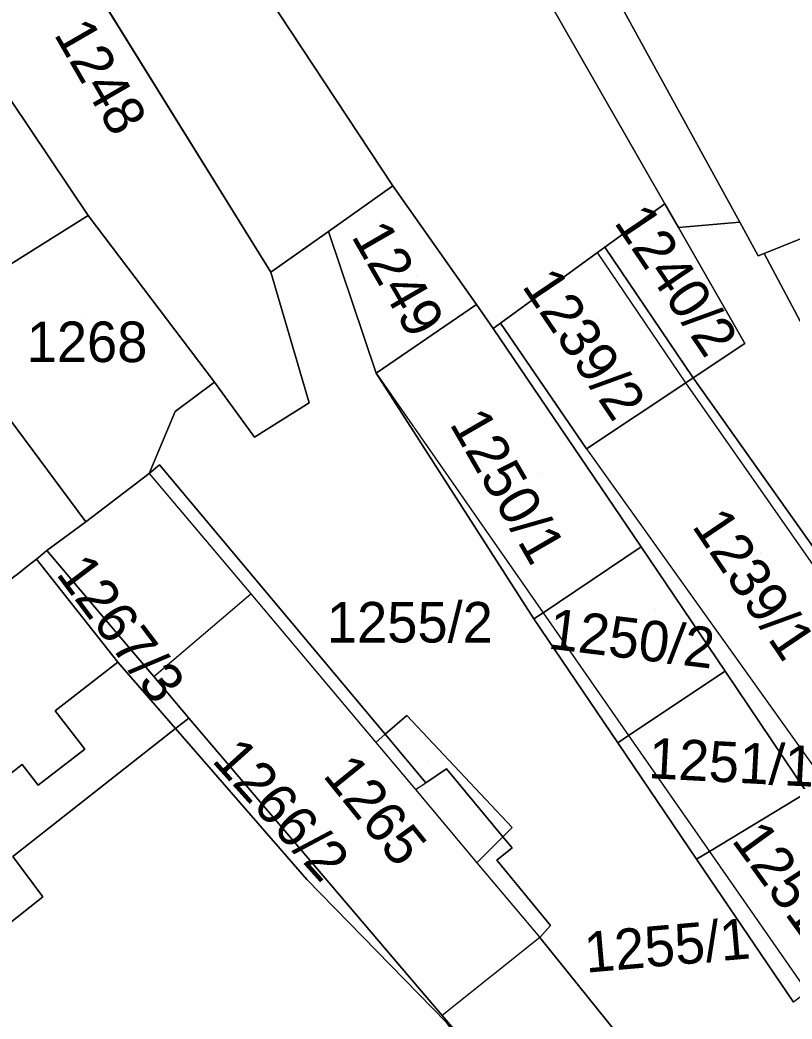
# Model space of a CAD drawing. Extents: x -263943 to -261149, y -1236934 to -1230686.
# Drawn here: x -263003.38 to -262965.33, y -1235458.41 to -1235409.18 of the extents above; entities that cross this region are included whole.
import ezdxf

# ---------------------------------------------------------------- set-up
doc = ezdxf.new("R2010")
doc.units = 0
for name, color, linetype in [('body_kn', 7, 'Continuous'), ('kladpar_druhypozemkov', 7, 'Continuous'), ('kladpar_hranice', 7, 'Continuous'), ('kladpar_parcelnecisla', 7, 'Continuous'), ('kladpar_plochy', 7, 'Continuous'), ('kladpar_sipky', 7, 'Continuous'), ('zappar_hrandruhpozemk', 7, 'Continuous')]:
    doc.layers.add(name, color=color, linetype=linetype)

msp = doc.modelspace()

# ---------------------------------------------------------------- linework, layer by layer
at = {"layer": 'body_kn'}
for p, q in [((-262985, -1235417.35), (-262985, -1235417.35)), ((-262985, -1235417.35), (-262985, -1235417.35)), ((-262971.6, -1235418.24), (-262971.6, -1235418.24)), ((-262971.6, -1235418.24), (-262971.6, -1235418.24)), ((-263000.02, -1235418.81), (-263000.02, -1235418.81)), ((-262970.93, -1235419.41), (-262970.93, -1235419.41)), ((-262967.9, -1235419.14), (-262967.9, -1235419.14)), ((-262988.18, -1235419.6), (-262988.18, -1235419.6)), ((-262974.55, -1235420.38), (-262974.55, -1235420.38)), ((-262974.91, -1235420.64), (-262974.91, -1235420.64)), ((-262966.99, -1235420.8), (-262966.99, -1235420.8)), ((-262966.7, -1235420.68), (-262966.7, -1235420.68)), ((-262991.01, -1235421.6), (-262991.01, -1235421.6)), ((-262991.01, -1235421.6), (-262991.01, -1235421.6)), ((-262980.88, -1235423.2), (-262980.88, -1235423.2)), ((-262980.05, -1235424.38), (-262980.05, -1235424.38)), ((-262979.69, -1235424.12), (-262979.69, -1235424.12)), ((-262979.69, -1235424.12), (-262979.69, -1235424.12)), ((-262967.66, -1235425.12), (-262967.66, -1235425.12)), ((-262985.82, -1235426.59), (-262985.82, -1235426.59)), ((-262985.82, -1235426.59), (-262985.82, -1235426.59)), ((-262970.2, -1235426.82), (-262970.2, -1235426.82)), ((-262970.2, -1235426.82), (-262970.2, -1235426.82)), ((-262993.8, -1235427.03), (-262993.8, -1235427.03)), ((-262993.8, -1235427.03), (-262993.8, -1235427.03)), ((-262970.57, -1235427.06), (-262970.57, -1235427.06)), ((-262970.57, -1235427.06), (-262970.57, -1235427.06)), ((-262989.12, -1235428.04), (-262989.12, -1235428.04)), ((-262995.74, -1235428.47), (-262995.74, -1235428.47)), ((-262991.83, -1235429.74), (-262991.83, -1235429.74)), ((-262975.45, -1235430.31), (-262975.45, -1235430.31)), ((-262975.45, -1235430.31), (-262975.45, -1235430.31)), ((-262996.5, -1235431.1), (-262996.5, -1235431.1)), ((-262997.01, -1235431.53), (-262997.01, -1235431.53)), ((-262997.01, -1235431.53), (-262997.01, -1235431.53)), ((-263000.14, -1235433.91), (-263000.14, -1235433.91)), ((-263000.14, -1235433.91), (-263000.14, -1235433.91)), ((-262972.77, -1235435.14), (-262972.77, -1235435.14)), ((-263002.57, -1235435.75), (-263002.57, -1235435.75)), ((-263002.57, -1235435.75), (-263002.57, -1235435.75)), ((-263002.05, -1235435.33), (-263002.05, -1235435.33)), ((-263002.99, -1235436.08), (-263002.99, -1235436.08)), ((-263002.99, -1235436.08), (-263002.99, -1235436.08)), ((-262992.01, -1235437.46), (-262992.01, -1235437.46)), ((-262992.01, -1235437.46), (-262992.01, -1235437.46)), ((-262978.06, -1235438.7), (-262978.06, -1235438.7)), ((-262977.6, -1235438.39), (-262977.6, -1235438.39)), ((-262977.6, -1235438.39), (-262977.6, -1235438.39)), ((-262997.86, -1235440.27), (-262997.86, -1235440.27)), ((-262998.56, -1235440.83), (-262998.56, -1235440.83)), ((-262999.43, -1235441.5), (-262999.43, -1235441.5)), ((-262996.79, -1235441.54), (-262996.79, -1235441.54)), ((-262996.79, -1235441.54), (-262996.79, -1235441.54)), ((-262968.63, -1235441.27), (-262968.63, -1235441.27)), ((-263001.65, -1235443.23), (-263001.65, -1235443.23)), ((-262995.06, -1235443.59), (-262995.06, -1235443.59)), ((-262984.32, -1235443.46), (-262984.32, -1235443.46)), ((-262995.72, -1235444.1), (-262995.72, -1235444.1)), ((-262995.72, -1235444.1), (-262995.72, -1235444.1)), ((-262985.38, -1235444.38), (-262985.38, -1235444.38)), ((-262973.38, -1235444.45), (-262973.38, -1235444.45)), ((-262973.38, -1235444.45), (-262973.38, -1235444.45)), ((-263000.19, -1235445.11), (-263000.19, -1235445.11)), ((-262985.84, -1235444.79), (-262985.84, -1235444.79)), ((-262985.84, -1235444.79), (-262985.84, -1235444.79)), ((-262973.92, -1235444.81), (-262973.92, -1235444.81)), ((-262973.92, -1235444.81), (-262973.92, -1235444.81)), ((-263003.27, -1235445.87), (-263003.27, -1235445.87)), ((-262982.36, -1235446.09), (-262982.36, -1235446.09)), ((-262982.36, -1235446.09), (-262982.36, -1235446.09)), ((-263002.48, -1235446.89), (-263002.48, -1235446.89)), ((-262983.38, -1235446.77), (-262983.38, -1235446.77)), ((-262983.89, -1235447.11), (-262983.89, -1235447.11)), ((-262983.89, -1235447.11), (-262983.89, -1235447.11)), ((-262979.12, -1235448.97), (-262979.12, -1235448.97)), ((-262979.58, -1235449.43), (-262979.58, -1235449.43)), ((-262979.58, -1235449.43), (-262979.58, -1235449.43)), ((-262979.12, -1235449.98), (-262979.12, -1235449.98)), ((-262979.12, -1235449.98), (-262979.12, -1235449.98)), ((-262970.03, -1235450.54), (-262970.03, -1235450.54)), ((-262970.03, -1235450.54), (-262970.03, -1235450.54)), ((-262969.4, -1235450.16), (-262969.4, -1235450.16)), ((-262969.4, -1235450.16), (-262969.4, -1235450.16)), ((-262980.86, -1235450.71), (-262980.86, -1235450.71)), ((-262979.88, -1235450.58), (-262979.88, -1235450.58)), ((-262989.24, -1235451.54), (-262989.24, -1235451.54)), ((-263002.26, -1235452.39), (-263002.26, -1235452.39)), ((-262977.24, -1235453.8), (-262977.24, -1235453.8)), ((-262977.75, -1235454.39), (-262977.75, -1235454.39)), ((-262977.75, -1235454.39), (-262977.75, -1235454.39)), ((-262982.57, -1235458.24), (-262982.57, -1235458.24))]:
    msp.add_line(p, q, dxfattribs=at)
at = {"layer": 'kladpar_druhypozemkov'}
for p, q in [((-262970.63, -1235421.43), (-262970.63, -1235421.43)), ((-262983.83, -1235421.82), (-262983.83, -1235421.82)), ((-263000.34, -1235423.74), (-263000.34, -1235423.74)), ((-262974.88, -1235423.93), (-262974.88, -1235423.93)), ((-262977.82, -1235431.53), (-262977.82, -1235431.53)), ((-262966.9, -1235435.4), (-262966.9, -1235435.4)), ((-263001.05, -1235437.03), (-263001.05, -1235437.03)), ((-262972.04, -1235438.24), (-262972.04, -1235438.24)), ((-262969.12, -1235445.26), (-262969.12, -1235445.26)), ((-262983.25, -1235445.69), (-262983.25, -1235445.69)), ((-262993.23, -1235446.29), (-262993.23, -1235446.29)), ((-262985.11, -1235447.63), (-262985.11, -1235447.63)), ((-262972.94, -1235453.94), (-262972.94, -1235453.94))]:
    msp.add_line(p, q, dxfattribs=at)
at = {"layer": 'kladpar_hranice'}
msp.add_line((-262988.18, -1235419.6), (-262991.01, -1235421.6), dxfattribs=at)
for points in [[(-262991.01, -1235421.6), (-263006.36, -1235396.86), (-263012.04, -1235400.51), (-263013.75, -1235397.97), (-263020.74, -1235387.21), (-263026.28, -1235378.22), (-263034.8, -1235364.66), (-263018.87, -1235356.25), (-263013.95, -1235366.36), (-263010.5, -1235373.45), (-262997.36, -1235398.62), (-262985, -1235417.35), (-262988.18, -1235419.6)], [(-262971.6, -1235418.24), (-262986.86, -1235391.57), (-262995.81, -1235375.55), (-263001.69, -1235369.37), (-262997.27, -1235369.36), (-262996.85, -1235369.53), (-262994.9, -1235368.6), (-262991.76, -1235367.15), (-262991.67, -1235370.46), (-262991.57, -1235373.85), (-262990.55, -1235377.84), (-262980.56, -1235396.06), (-262967.9, -1235419.14), (-262970.93, -1235419.41), (-262971.6, -1235418.24)], [(-262959.63, -1235414.42), (-262958.44, -1235417.35), (-262966.7, -1235420.68), (-262966.99, -1235420.8), (-262967.9, -1235419.14), (-262980.56, -1235396.06), (-262970.22, -1235390.61), (-262963.9, -1235405.36), (-262962.96, -1235407.48), (-262959.63, -1235414.42)], [(-262979.69, -1235424.12), (-262980.05, -1235424.38), (-262980.88, -1235423.2), (-262985, -1235417.35), (-262997.36, -1235398.62), (-262986.86, -1235391.57), (-262971.6, -1235418.24), (-262974.55, -1235420.38), (-262974.91, -1235420.64), (-262979.69, -1235424.12)], [(-262993.8, -1235427.03), (-263000.02, -1235418.81), (-263005.72, -1235410.34), (-263007.22, -1235408.16), (-263012.04, -1235400.51), (-263006.36, -1235396.86), (-262991.01, -1235421.6), (-262989.12, -1235428.04), (-262991.83, -1235429.74), (-262993.8, -1235427.03)], [(-263028.99, -1235436.97), (-263030.68, -1235438.03), (-263032.22, -1235434.75), (-263022.27, -1235429.8), (-263021.19, -1235431.41), (-263016.12, -1235428.08), (-263018.16, -1235424.78), (-263022.63, -1235427.75), (-263022.6, -1235425.3), (-263016.14, -1235421.87), (-263016.64, -1235420.94), (-263012.58, -1235418.83), (-263013.18, -1235417.56), (-263005.72, -1235410.34), (-263000.02, -1235418.81), (-263007.76, -1235423.66), (-263028.99, -1235436.97)], [(-262985, -1235417.35), (-262980.88, -1235423.2), (-262985.82, -1235426.59), (-262988.18, -1235419.6), (-262985, -1235417.35)], [(-262956.21, -1235422.81), (-262953.64, -1235429.76), (-262960.42, -1235432.49), (-262966.7, -1235420.68), (-262958.44, -1235417.35), (-262957.93, -1235418.59), (-262957.75, -1235419.04), (-262956.21, -1235422.81)], [(-262970.2, -1235426.82), (-262974.55, -1235420.38), (-262971.6, -1235418.24), (-262970.93, -1235419.41), (-262967.66, -1235425.12), (-262970.2, -1235426.82)], [(-263000.14, -1235433.91), (-263007.76, -1235423.66), (-263000.02, -1235418.81), (-262993.8, -1235427.03), (-262995.74, -1235428.47), (-262997.01, -1235431.53), (-263000.14, -1235433.91)], [(-262950.87, -1235452.84), (-262947.38, -1235460.65), (-262944.89, -1235466.22), (-262947.49, -1235467.99), (-262942.82, -1235478.02), (-262939.2, -1235485.83), (-262943.02, -1235478.13), (-262948, -1235468.07), (-262950.21, -1235463.4), (-262953.13, -1235457.23), (-262956.06, -1235451.05), (-262956.46, -1235450.2), (-262957.6, -1235445.57), (-262957.16, -1235445.2), (-262970.2, -1235426.82), (-262967.66, -1235425.12), (-262970.93, -1235419.41), (-262967.9, -1235419.14), (-262966.99, -1235420.8), (-262966.7, -1235420.68), (-262960.42, -1235432.49), (-262954.79, -1235442.65), (-262955.3, -1235442.91), (-262950.87, -1235452.84)], [(-262973.06, -1235460.23), (-262977.75, -1235454.39), (-262977.24, -1235453.8), (-262979.88, -1235450.58), (-262979.12, -1235449.98), (-262979.58, -1235449.43), (-262979.12, -1235448.97), (-262984.32, -1235443.46), (-262985.38, -1235444.38), (-262996.5, -1235431.1), (-262997.01, -1235431.53), (-262995.74, -1235428.47), (-262993.8, -1235427.03), (-262991.83, -1235429.74), (-262989.12, -1235428.04), (-262991.01, -1235421.6), (-262988.18, -1235419.6), (-262985.82, -1235426.59), (-262978.06, -1235438.7), (-262973.92, -1235444.81), (-262970.03, -1235450.54), (-262965.26, -1235457.59)], [(-262979.69, -1235424.12), (-262974.91, -1235420.64), (-262974.55, -1235420.38), (-262970.2, -1235426.82), (-262970.57, -1235427.06), (-262975.45, -1235430.31), (-262979.69, -1235424.12)], [(-262977.6, -1235438.39), (-262978.06, -1235438.7), (-262985.82, -1235426.59), (-262980.88, -1235423.2), (-262980.05, -1235424.38), (-262972.77, -1235435.14), (-262977.6, -1235438.39)], [(-263002.99, -1235436.08), (-263003.52, -1235436.5), (-263003.62, -1235436.58), (-263011.28, -1235442.62), (-263021.64, -1235450.8), (-263023.21, -1235451.7), (-263025.64, -1235447.26), (-263027.27, -1235444.21), (-263027.78, -1235443.11), (-263030.68, -1235438.03), (-263028.99, -1235436.97), (-263007.76, -1235423.66), (-263000.14, -1235433.91), (-263002.05, -1235435.33), (-263002.57, -1235435.75), (-263002.99, -1235436.08)], [(-262961.15, -1235452.34), (-262964.59, -1235447.25), (-262968.63, -1235441.27), (-262972.77, -1235435.14), (-262980.05, -1235424.38), (-262979.69, -1235424.12), (-262975.45, -1235430.31), (-262970.57, -1235427.06), (-262970.2, -1235426.82), (-262957.16, -1235445.2), (-262957.6, -1235445.57), (-262956.46, -1235450.2), (-262961.15, -1235452.34)], [(-262979.12, -1235449.98), (-262979.88, -1235450.58), (-262977.24, -1235453.8), (-262977.75, -1235454.39), (-262973.06, -1235460.23), (-262977.46, -1235463.99), (-262979.42, -1235461.94), (-262982.57, -1235458.24), (-262995.06, -1235443.59), (-262996.79, -1235441.54), (-262997.86, -1235440.27), (-263002.05, -1235435.33), (-263000.14, -1235433.91), (-262997.01, -1235431.53), (-262996.5, -1235431.1), (-262985.38, -1235444.38), (-262983.38, -1235446.77), (-262982.36, -1235446.09), (-262979.58, -1235449.43), (-262979.12, -1235449.98)], [(-262973.92, -1235444.81), (-262978.06, -1235438.7), (-262977.6, -1235438.39), (-262972.77, -1235435.14), (-262968.63, -1235441.27), (-262973.38, -1235444.45), (-262973.92, -1235444.81)], [(-263021.64, -1235450.8), (-263011.28, -1235442.62), (-263003.62, -1235436.58), (-263003.52, -1235436.5), (-263002.99, -1235436.08), (-263002.57, -1235435.75), (-262998.56, -1235440.83), (-262999.43, -1235441.5), (-263001.65, -1235443.23), (-263000.19, -1235445.11), (-263002.48, -1235446.89), (-263003.27, -1235445.87), (-263006.08, -1235448.06), (-263006.74, -1235447.2), (-263007.82, -1235448.04), (-263007.16, -1235448.9), (-263008.79, -1235450.17), (-263014.93, -1235454.95), (-263015.6, -1235454.1), (-263017.55, -1235455.62), (-263021.64, -1235450.8)], [(-263002.57, -1235435.75), (-263002.05, -1235435.33), (-262997.86, -1235440.27), (-262996.79, -1235441.54), (-262995.06, -1235443.59), (-262995.72, -1235444.1), (-262998.56, -1235440.83), (-263002.57, -1235435.75)], [(-263023.21, -1235451.7), (-263021.64, -1235450.8), (-263017.55, -1235455.62), (-263015.6, -1235454.1), (-263014.93, -1235454.95), (-263008.79, -1235450.17), (-263007.16, -1235448.9), (-263007.82, -1235448.04), (-263006.74, -1235447.2), (-263006.08, -1235448.06), (-263003.27, -1235445.87), (-263002.48, -1235446.89), (-263000.19, -1235445.11), (-263001.65, -1235443.23), (-262999.43, -1235441.5), (-262998.56, -1235440.83), (-262995.72, -1235444.1), (-263003.74, -1235450.41), (-263002.26, -1235452.39), (-263008.03, -1235456.98), (-263009.2, -1235455.44), (-263014.53, -1235459.53)], [(-262970.03, -1235450.54), (-262973.92, -1235444.81), (-262973.38, -1235444.45), (-262968.63, -1235441.27), (-262964.59, -1235447.25), (-262969.4, -1235450.16), (-262970.03, -1235450.54)], [(-262995.72, -1235444.1), (-262995.06, -1235443.59), (-262982.57, -1235458.24), (-262979.42, -1235461.94), (-262985.77, -1235466.77), (-263002.85, -1235479.75), (-263003.17, -1235479.37), (-262979.92, -1235461.83), (-262982.36, -1235458.59), (-262989.24, -1235451.54), (-262995.72, -1235444.1)], [(-262982.36, -1235446.09), (-262983.38, -1235446.77), (-262985.38, -1235444.38), (-262984.32, -1235443.46), (-262979.12, -1235448.97), (-262979.58, -1235449.43), (-262982.36, -1235446.09)], [(-263015.82, -1235464.26), (-263012.73, -1235461.95), (-263014.53, -1235459.53), (-263009.2, -1235455.44), (-263008.03, -1235456.98), (-263002.26, -1235452.39), (-263003.74, -1235450.41), (-262995.72, -1235444.1), (-262989.24, -1235451.54), (-262982.36, -1235458.59), (-262979.92, -1235461.83), (-263003.17, -1235479.37), (-263015.82, -1235464.26)], [(-262959.84, -1235454.28), (-262964.58, -1235457.08), (-262965.26, -1235457.59), (-262970.03, -1235450.54), (-262969.4, -1235450.16), (-262964.59, -1235447.25), (-262961.15, -1235452.34), (-262960.63, -1235453.11), (-262959.84, -1235454.28)]]:
    msp.add_lwpolyline(points, dxfattribs=at)
at = {"layer": 'kladpar_plochy'}
for p, q in [((-262991.01, -1235421.6), (-263006.36, -1235396.86)), ((-262997.36, -1235398.62), (-262985, -1235417.35)), ((-262985, -1235417.35), (-262988.18, -1235419.6)), ((-262988.18, -1235419.6), (-262991.01, -1235421.6))]:
    msp.add_line(p, q, dxfattribs=at)
for points in [[(-262971.6, -1235418.24), (-262986.86, -1235391.57), (-262995.81, -1235375.55), (-263001.69, -1235369.37), (-262997.27, -1235369.36), (-262996.85, -1235369.53), (-262994.9, -1235368.6), (-262991.76, -1235367.15), (-262991.67, -1235370.46), (-262991.57, -1235373.85), (-262990.55, -1235377.84), (-262980.56, -1235396.06), (-262967.9, -1235419.14), (-262970.93, -1235419.41)], [(-262959.63, -1235414.42), (-262958.44, -1235417.35), (-262966.7, -1235420.68), (-262966.99, -1235420.8), (-262967.9, -1235419.14), (-262980.56, -1235396.06), (-262970.22, -1235390.61), (-262963.9, -1235405.36), (-262962.96, -1235407.48)], [(-262979.69, -1235424.12), (-262980.05, -1235424.38), (-262980.88, -1235423.2), (-262985, -1235417.35), (-262997.36, -1235398.62), (-262986.86, -1235391.57), (-262971.6, -1235418.24), (-262974.55, -1235420.38), (-262974.91, -1235420.64)], [(-262993.8, -1235427.03), (-263000.02, -1235418.81), (-263005.72, -1235410.34), (-263007.22, -1235408.16), (-263012.04, -1235400.51), (-263006.36, -1235396.86), (-262991.01, -1235421.6), (-262989.12, -1235428.04), (-262991.83, -1235429.74)], [(-263028.99, -1235436.97), (-263030.68, -1235438.03), (-263032.22, -1235434.75), (-263022.27, -1235429.8), (-263021.19, -1235431.41), (-263016.12, -1235428.08), (-263018.16, -1235424.78), (-263022.63, -1235427.75), (-263022.6, -1235425.3), (-263016.14, -1235421.87), (-263016.64, -1235420.94), (-263012.58, -1235418.83), (-263013.18, -1235417.56), (-263005.72, -1235410.34), (-263000.02, -1235418.81), (-263007.76, -1235423.66)], [(-262985, -1235417.35), (-262980.88, -1235423.2), (-262985.82, -1235426.59), (-262988.18, -1235419.6)], [(-262956.21, -1235422.81), (-262953.64, -1235429.76), (-262960.42, -1235432.49), (-262966.7, -1235420.68), (-262958.44, -1235417.35), (-262957.93, -1235418.59), (-262957.75, -1235419.04)], [(-262970.2, -1235426.82), (-262974.55, -1235420.38), (-262971.6, -1235418.24), (-262970.93, -1235419.41), (-262967.66, -1235425.12)], [(-263000.14, -1235433.91), (-263007.76, -1235423.66), (-263000.02, -1235418.81), (-262993.8, -1235427.03), (-262995.74, -1235428.47), (-262997.01, -1235431.53)], [(-262950.87, -1235452.84), (-262947.38, -1235460.65), (-262944.89, -1235466.22), (-262947.49, -1235467.99), (-262942.82, -1235478.02), (-262939.2, -1235485.83), (-262943.02, -1235478.13), (-262948, -1235468.07), (-262950.21, -1235463.4), (-262953.13, -1235457.23), (-262956.06, -1235451.05), (-262956.46, -1235450.2), (-262957.6, -1235445.57), (-262957.16, -1235445.2), (-262970.2, -1235426.82), (-262967.66, -1235425.12), (-262970.93, -1235419.41), (-262967.9, -1235419.14), (-262966.99, -1235420.8), (-262966.7, -1235420.68), (-262960.42, -1235432.49), (-262954.79, -1235442.65), (-262955.3, -1235442.91)], [(-262979.69, -1235424.12), (-262974.91, -1235420.64), (-262974.55, -1235420.38), (-262970.2, -1235426.82), (-262970.57, -1235427.06), (-262975.45, -1235430.31)], [(-262977.6, -1235438.39), (-262978.06, -1235438.7), (-262985.82, -1235426.59), (-262980.88, -1235423.2), (-262980.05, -1235424.38), (-262972.77, -1235435.14)], [(-263002.99, -1235436.08), (-263003.52, -1235436.5), (-263003.62, -1235436.58), (-263011.28, -1235442.62), (-263021.64, -1235450.8), (-263023.21, -1235451.7), (-263025.64, -1235447.26), (-263027.27, -1235444.21), (-263027.78, -1235443.11), (-263030.68, -1235438.03), (-263028.99, -1235436.97), (-263007.76, -1235423.66), (-263000.14, -1235433.91), (-263002.05, -1235435.33), (-263002.57, -1235435.75)], [(-262961.15, -1235452.34), (-262964.59, -1235447.25), (-262968.63, -1235441.27), (-262972.77, -1235435.14), (-262980.05, -1235424.38), (-262979.69, -1235424.12), (-262975.45, -1235430.31), (-262970.57, -1235427.06), (-262970.2, -1235426.82), (-262957.16, -1235445.2), (-262957.6, -1235445.57), (-262956.46, -1235450.2)], [(-262979.12, -1235449.98), (-262979.88, -1235450.58), (-262977.24, -1235453.8), (-262977.75, -1235454.39), (-262973.06, -1235460.23), (-262977.46, -1235463.99), (-262979.42, -1235461.94), (-262982.57, -1235458.24), (-262995.06, -1235443.59), (-262996.79, -1235441.54), (-262997.86, -1235440.27), (-263002.05, -1235435.33), (-263000.14, -1235433.91), (-262997.01, -1235431.53), (-262996.5, -1235431.1), (-262985.38, -1235444.38), (-262983.38, -1235446.77), (-262982.36, -1235446.09), (-262979.58, -1235449.43)], [(-262973.92, -1235444.81), (-262978.06, -1235438.7), (-262977.6, -1235438.39), (-262972.77, -1235435.14), (-262968.63, -1235441.27), (-262973.38, -1235444.45)], [(-263021.64, -1235450.8), (-263011.28, -1235442.62), (-263003.62, -1235436.58), (-263003.52, -1235436.5), (-263002.99, -1235436.08), (-263002.57, -1235435.75), (-262998.56, -1235440.83), (-262999.43, -1235441.5), (-263001.65, -1235443.23), (-263000.19, -1235445.11), (-263002.48, -1235446.89), (-263003.27, -1235445.87), (-263006.08, -1235448.06), (-263006.74, -1235447.2), (-263007.82, -1235448.04), (-263007.16, -1235448.9), (-263008.79, -1235450.17), (-263014.93, -1235454.95), (-263015.6, -1235454.1), (-263017.55, -1235455.62)], [(-263002.57, -1235435.75), (-263002.05, -1235435.33), (-262997.86, -1235440.27), (-262996.79, -1235441.54), (-262995.06, -1235443.59), (-262995.72, -1235444.1), (-262998.56, -1235440.83)], [(-262970.03, -1235450.54), (-262973.92, -1235444.81), (-262973.38, -1235444.45), (-262968.63, -1235441.27), (-262964.59, -1235447.25), (-262969.4, -1235450.16)], [(-262995.72, -1235444.1), (-262995.06, -1235443.59), (-262982.57, -1235458.24), (-262979.42, -1235461.94), (-262985.77, -1235466.77), (-263002.85, -1235479.75), (-263003.17, -1235479.37), (-262979.92, -1235461.83), (-262982.36, -1235458.59), (-262989.24, -1235451.54)], [(-262982.36, -1235446.09), (-262983.38, -1235446.77), (-262985.38, -1235444.38), (-262984.32, -1235443.46), (-262979.12, -1235448.97), (-262979.58, -1235449.43)], [(-263015.82, -1235464.26), (-263012.73, -1235461.95), (-263014.53, -1235459.53), (-263009.2, -1235455.44), (-263008.03, -1235456.98), (-263002.26, -1235452.39), (-263003.74, -1235450.41), (-262995.72, -1235444.1), (-262989.24, -1235451.54), (-262982.36, -1235458.59), (-262979.92, -1235461.83), (-263003.17, -1235479.37)], [(-262959.84, -1235454.28), (-262964.58, -1235457.08), (-262965.26, -1235457.59), (-262970.03, -1235450.54), (-262969.4, -1235450.16), (-262964.59, -1235447.25), (-262961.15, -1235452.34), (-262960.63, -1235453.11)]]:
    msp.add_lwpolyline(points, close=True, dxfattribs=at)
for points in [[(-262973.06, -1235460.23), (-262977.75, -1235454.39), (-262977.24, -1235453.8), (-262979.88, -1235450.58), (-262979.12, -1235449.98), (-262979.58, -1235449.43), (-262979.12, -1235448.97), (-262984.32, -1235443.46), (-262985.38, -1235444.38), (-262996.5, -1235431.1), (-262997.01, -1235431.53), (-262995.74, -1235428.47), (-262993.8, -1235427.03), (-262991.83, -1235429.74), (-262989.12, -1235428.04), (-262991.01, -1235421.6), (-262988.18, -1235419.6), (-262985.82, -1235426.59), (-262978.06, -1235438.7), (-262973.92, -1235444.81), (-262970.03, -1235450.54), (-262965.26, -1235457.59)], [(-263017.04, -1235462.8), (-263019.98, -1235457.51), (-263023.21, -1235451.7), (-263021.64, -1235450.8), (-263017.55, -1235455.62), (-263015.6, -1235454.1), (-263014.93, -1235454.95), (-263008.79, -1235450.17), (-263007.16, -1235448.9), (-263007.82, -1235448.04), (-263006.74, -1235447.2), (-263006.08, -1235448.06), (-263003.27, -1235445.87), (-263002.48, -1235446.89), (-263000.19, -1235445.11), (-263001.65, -1235443.23), (-262999.43, -1235441.5), (-262998.56, -1235440.83), (-262995.72, -1235444.1), (-263003.74, -1235450.41), (-263002.26, -1235452.39), (-263008.03, -1235456.98), (-263009.2, -1235455.44), (-263014.53, -1235459.53)]]:
    msp.add_lwpolyline(points, dxfattribs=at)
at = {"layer": 'kladpar_sipky'}
msp.add_line((-262983.68, -1235444.4), (-262983.68, -1235444.4), dxfattribs=at)
at = {"layer": 'zappar_hrandruhpozemk'}
for p, q in [((-262970.57, -1235427.06), (-262974.91, -1235420.64)), ((-262985.82, -1235426.59), (-262977.6, -1235438.39)), ((-262997.01, -1235431.53), (-262992.01, -1235437.46)), ((-262996.79, -1235441.54), (-262992.01, -1235437.46)), ((-262977.6, -1235438.39), (-262973.38, -1235444.45)), ((-262985.84, -1235444.79), (-262985.38, -1235444.38)), ((-262973.38, -1235444.45), (-262969.4, -1235450.16)), ((-262983.89, -1235447.11), (-262983.38, -1235446.77)), ((-262979.58, -1235449.43), (-262980.86, -1235450.71)), ((-262969.4, -1235450.16), (-262964.58, -1235457.08)), ((-262977.75, -1235454.39), (-262982.57, -1235458.24))]:
    msp.add_line(p, q, dxfattribs=at)
for points in [[(-262975.45, -1235430.31), (-262962.58, -1235448.34), (-262957.92, -1235445.12), (-262970.57, -1235427.06)], [(-262992.01, -1235437.46), (-262985.84, -1235444.79), (-262983.89, -1235447.11), (-262980.86, -1235450.71), (-262977.75, -1235454.39)]]:
    msp.add_lwpolyline(points, dxfattribs=at)

# ---------------------------------------------------------------- texts
at = {"layer": 'kladpar_parcelnecisla'}
for s, rotation, p in [('1248', 300, (-263001.741, -1235409.876)), ('1240/2', 304, (-262974.137, -1235419.148)), ('1249', 300, (-262987.08, -1235419.836)), ('1239/2', 304, (-262978.676, -1235422.289)), ('1250/1', 300, (-262982.238, -1235429.079)), ('1239/1', 304, (-262970.299, -1235434.121)), ('1267/3', 307, (-263001.646, -1235436.482)), ('1250/2', 353, (-262977.407, -1235440.15)), ('1251/1', 357, (-262972.441, -1235446.542)), ('1266/2', 312, (-262993.97, -1235445.7)), ('1265', 309, (-262988.496, -1235446.42)), ('1251/2', 306, (-262968.343, -1235449.612)), ('1255/1', 5, (-262975.475, -1235456.135))]:
    msp.add_text(s, height=2, rotation=rotation, dxfattribs=at).set_placement(p)
for s, p in [('1268', (-263003.051, -1235426.04)), ('1255/2', (-262988.254, -1235439.86))]:
    msp.add_text(s, height=2, dxfattribs=at).set_placement(p)

doc.saveas('drawing.dxf')
